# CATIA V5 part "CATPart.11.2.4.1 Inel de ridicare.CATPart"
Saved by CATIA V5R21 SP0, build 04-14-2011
Part number: Inel de ridicare şurub
Bounding box of the stored display mesh (mm): x -9.942 to 9.942, y -16.097 to 16.097, z -15 to 35.933
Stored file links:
  C:\Users\MIRCEA\Desktop\MOM\Mogan\model\CATPart.11.2.4.1 Inel de ridicare.CATPart
  C:\Program Files (x86)\Dassault Systemes\B21\intel_a\reffiles\standard\MetricThinPitch.txt
  C:\Program Files (x86)\Dassault Systemes\B21\intel_a\reffiles\standard\MetricThickPitch.txt
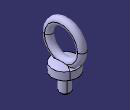
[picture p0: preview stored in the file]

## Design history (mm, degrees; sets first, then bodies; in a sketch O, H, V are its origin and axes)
Parameters
  d = 8 mm
  d1 = 20 mm
  d3 = 32.5 mm
  l = 15 mm
  h = 20 mm
  e = 6 mm
  b = 6.3 mm
  c = 1.8 mm
Body1 (main body)
  Sketch1 on yz-plane, origin (0, 0, 0), H (0, 1, 0), V (0, 0, 1)
    circle A1 centre (0, 20) radius 13.125
    point P1 (0, 20)
    distance P1 H = 20 {= h}
    radius A1 = 13.125 {= (d3 +d1 )/4}
    coincidence: P1 V
  Sketch2 on zx-plane, origin (0, 0, 0), H (-1, 0, 0), V (0, 0, 1)
    circle A1 centre (0, 33.125) radius 3.125
    point P1 (0, 33.125)
    radius A1 = 3.125 {= (d3 -d1 )/4}
    distance P1 H = 33.125 {= h +(d3+d1)/4}
    coincidence: P1 V
  Rib1: profile Sketch2, centre curve Sketch1
  Sketch3 on yz-plane, origin (0, 0, 0), H (0, 1, 0), V (0, 0, 1)
    line L1 (-10, 6) -> (-10, 0)
    point P2 (-10, 0)
    line L2 (-10, 0) -> (-3, 0)
    construction line L3 (-10, 6) -> (0, 6)
    point P3 (0, 6)
    arc A1 centre (0, -18) radius 26 from (-10, 6) to (0, 8) cw
    point P4 (0, -18)
    point P5 (0, 8)
    line L4 (-3, 0) -> (-3, -3)
    line L5 (-3, -3) -> (-4, -3)
    line L6 (-4, -3) -> (-4, -13.2)
    line L7 (-2.2, -15) -> (0, -15)
    point P9 (0, -15)
    axis line L8 (0, 10.2118) -> (0, -15)
    point P10 (0, 10.2118)
    line L9 (-4, -13.2) -> (-2.2, -15)
    point P11 (-4, -13.2)
    point P13 (-4, -15)
    length L1 = 6 {= e}
    distance P5 H = 8 {= h -deleted_d2 /2}
    distance L1 V = 10 {= d1 /2}
    distance L7 L2 = 15 {= l}
    distance L6 V = 4 {= d /2}
    distance L2 L5 = 3
    distance L4 V = 3 {= Sketch3.distance(L6 V) -1mm}
    distance P11 P13 = 1.8 {= c}
    angle L6 L9 = 45
    coincidence: P2 H, P3 V, P5 V, P4 V, P9 V, P10 V, L6 P13, L7 P13
    vertical: L1 V, L4 V, L6 V, L8 V
    horizontal: L2 H, L3 H, L5 H, L7 H
  Shaft1: profile Sketch3, axis Sketch3.L8, angle 360
  Thread1: "M8", diameter 8, depth 12, pitch 1.25, on face of Shaft1 from Sketch3.L6, from face of Shaft1 from Sketch3.L7
Relations
  rule "Metric":
    /*Rule created by BEV 05.04.2020*/
    if d ==8 mm Thread1.ThreadDescription = "M8"
    	else if d ==10 mm Thread1.ThreadDescription = "M10"
    	else if d ==12 mm Thread1.ThreadDescription = "M12"
    	else if d ==14 mm Thread1.ThreadDescription = "M14"
    	else if d ==16 mm Thread1.ThreadDescription = "M16"
    	else if d ==18 mm Thread1.ThreadDescription = "M18"
    	else if d ==20 mm Thread1.ThreadDescription = "M20"
    	else if d ==22 mm Thread1.ThreadDescription = "M22"
    	else if d ==24 mm Thread1.ThreadDescription = "M24"
    	else if d ==27 mm Thread1.ThreadDescription = "M27"
    	else if d ==33 mm Thread1.ThreadDescription = "M33"
    	else if d ==36 mm Thread1.ThreadDescription = "M36"
    	else if d ==39 mm Thread1.ThreadDescription = "M39"
    	else if d ==42 mm Thread1.ThreadDescription = "M42"
    	else if d ==45 mm Thread1.ThreadDescription = "M45"
    	else if d ==48 mm Thread1.ThreadDescription = "M48"
    	else if d ==52 mm Thread1.ThreadDescription = "M52"
    	else if d ==56 mm Thread1.ThreadDescription = "M56"
    	else if d ==60 mm Thread1.ThreadDescription = "M60"
    	else if d ==64 mm Thread1.ThreadDescription = "M64"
